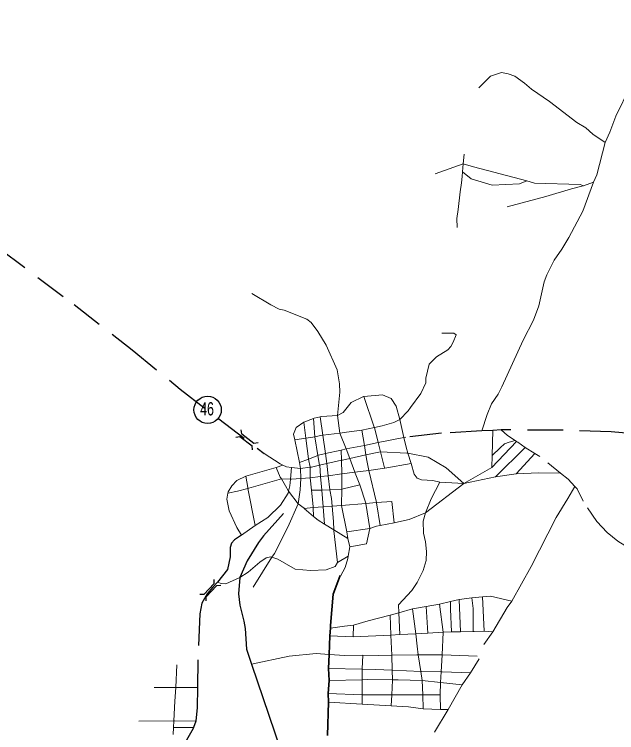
# Model space of a CAD drawing. Extents: x 423 to 448.8, y 7456.3 to 7484.
# Drawn here: x 441.806 to 445.463, y 7458.991 to 7463.35 of the extents above; entities that cross this region are included whole.
import ezdxf
from ezdxf.enums import TextEntityAlignment as Align

# ---------------------------------------------------------------- set-up
doc = ezdxf.new("R2010")
doc.units = 0
doc.header["$LTSCALE"] = 0.032
doc.linetypes.add('LONG_DASHED', pattern=[7.5, 6, -1.5])
doc.linetypes.add('MEDIUM_DASHED', pattern=[4.5, 3, -1.5])
for name, color, linetype, lineweight in [('10', 7, 'Continuous', 25), ('13', 7, 'Continuous', 25), ('15', 7, 'Continuous', 25), ('2', 7, 'Continuous', 35), ('4', 7, 'LONG_DASHED', 25), ('5', 7, 'LONG_DASHED', 13), ('6', 7, 'MEDIUM_DASHED', 13), ('7', 7, 'Continuous', 13), ('8', 7, 'Continuous', 13)]:
    doc.layers.add(name, color=color, linetype=linetype, lineweight=lineweight)
doc.layers.add('61', color=7, linetype='Continuous')

msp = doc.modelspace()

# ---------------------------------------------------------------- linework, layer by layer
at = {"layer": '10'}
for p, q in [((443.1866, 7460.8036), (443.1831, 7460.8283)), ((443.1501, 7460.7839), (443.1746, 7460.7876)), ((443.1746, 7460.7876), (443.2488, 7460.7324)), ((443.2525, 7460.7077), (443.2488, 7460.7324)), ((442.9705, 7459.8155), (443.0342, 7459.8825)), ((443.0592, 7459.8832), (443.0342, 7459.8825)), ((442.956, 7459.8292), (442.9311, 7459.8288)), ((442.9712, 7459.7907), (442.9705, 7459.8155))]:
    msp.add_line(p, q, dxfattribs=at)
for points in [[(443.1866, 7460.8036), (443.2608, 7460.7484), (443.2855, 7460.752)], [(442.956, 7459.8292), (443.0197, 7459.8963), (443.0191, 7459.9213)]]:
    msp.add_lwpolyline(points, dxfattribs=at)
at = {"layer": '13'}
msp.add_circle((442.9795, 7460.9502), 0.083, dxfattribs=at)
at = {"layer": '15'}
msp.add_lwpolyline([(443.4399, 7460.3212), (443.3192, 7460.186), (443.2888, 7460.1444), (443.2185, 7460.0341), (443.1755, 7459.9315), (443.1664, 7459.834), (443.1747, 7459.7637), (443.1986, 7459.6682), (443.2077, 7459.6227), (443.2157, 7459.4976), (443.2466, 7459.4065), (443.3513, 7459.0974), (443.4241, 7458.8825)], dxfattribs=at)
at = {"layer": '2'}
msp.add_lwpolyline([(443.7841, 7459.9454), (443.7413, 7459.8304), (443.7261, 7459.6406), (443.7247, 7459.6256), (443.7204, 7459.5783), (443.7165, 7459.4659), (443.7135, 7459.3795), (443.7181, 7459.3082), (443.7106, 7459.229), (443.7131, 7459.1759), (443.7079, 7458.9733)], dxfattribs=at)
at = {"layer": '4'}
for points in [[(439.8809, 7463.4977), (439.941, 7463.3465), (439.9475, 7463.3074), (439.9461, 7463.2713), (440.0002, 7463.2519), (440.0853, 7463.2005), (440.6229, 7462.7659), (440.6856, 7462.7187), (440.7238, 7462.6981), (440.7575, 7462.6654), (440.987, 7462.492), (441.1811, 7462.3354), (441.3202, 7462.2232), (441.6114, 7462.0058), (441.6724, 7461.9545), (441.7153, 7461.9277), (442.1688, 7461.5884), (442.5212, 7461.3144), (442.8129, 7461.0757), (443.0484, 7460.8955), (443.3233, 7460.6842)], [(445.5939, 7460.8017), (445.429, 7460.8155), (445.1129, 7460.8267), (444.7608, 7460.8281), (444.712, 7460.8254), (444.6433, 7460.8215), (444.3984, 7460.8078), (444.1834, 7460.784)], [(443.1856, 7460.1903), (443.1416, 7460.1609), (443.1247, 7460.1402), (443.1167, 7460.1151), (443.1165, 7460.0571), (443.1, 7459.9818), (443.0398, 7459.9036), (443.0108, 7459.8732), (442.9765, 7459.8343), (442.9443, 7459.7763), (442.9315, 7459.7119), (442.9194, 7459.4337), (442.9179, 7459.2659), (442.9168, 7459.1434), (442.9073, 7459.0609), (442.8937, 7459.0222), (442.8916, 7459.017), (442.8511, 7458.9445)]]:
    msp.add_lwpolyline(points, dxfattribs=at)
at = {"layer": '5'}
msp.add_lwpolyline([(443.2484, 7461.6551), (443.3632, 7461.587), (443.4134, 7461.5601), (443.4451, 7461.5541), (443.5825, 7461.5), (443.6074, 7461.4794), (443.6495, 7461.4262), (443.7001, 7461.3417), (443.7655, 7461.1933), (443.7808, 7461.1078), (443.7823, 7461.0565), (443.7687, 7460.9163)], dxfattribs=at)
at = {"layer": '6'}
msp.add_lwpolyline([(445.687, 7460.0021), (445.555, 7460.1006), (445.4699, 7460.1526), (445.4053, 7460.206), (445.3418, 7460.2718), (445.2585, 7460.3961), (445.2222, 7460.4702), (445.2083, 7460.4855), (445.1688, 7460.5289), (445.1225, 7460.5647), (444.9972, 7460.6675), (444.9652, 7460.6849), (444.9077, 7460.7213), (444.8634, 7460.7534), (444.8557, 7460.7584), (444.8458, 7460.7648), (444.8001, 7460.7943), (444.7608, 7460.8281)], dxfattribs=at)
at = {"layer": '7'}
msp.add_line((445.3218, 7462.3319), (445.2609, 7462.3096), dxfattribs=at)
for points in [[(445.3932, 7462.5717), (445.4216, 7462.6344), (445.4568, 7462.7319), (445.5458, 7462.9103), (445.6652, 7463.0789), (445.7851, 7463.2073)], [(445.3932, 7462.5717), (445.3178, 7462.6225), (445.2752, 7462.6618), (445.2211, 7462.6929), (445.0557, 7462.8205), (444.946, 7462.8968), (444.9034, 7462.9313), (444.8444, 7462.9739), (444.8035, 7462.9895), (444.7641, 7462.9977), (444.697, 7462.9747), (444.6266, 7462.9042)], [(445.3218, 7462.3319), (445.3424, 7462.376), (445.3932, 7462.5717)], [(444.5371, 7462.501), (444.531, 7462.4431), (444.531, 7462.4426), (444.5274, 7462.395)], [(444.917, 7462.3386), (444.5929, 7462.4239), (444.5316, 7462.4428), (444.531, 7462.4426), (444.3599, 7462.3827)], [(444.5274, 7462.395), (444.5253, 7462.3654), (444.5214, 7462.3281), (444.5117, 7462.2737), (444.4999, 7462.1648), (444.4923, 7462.1104), (444.4936, 7462.0567)], [(444.5274, 7462.395), (444.579, 7462.3525), (444.7074, 7462.3127), (444.8737, 7462.3214), (444.917, 7462.3386)], [(444.6433, 7460.8215), (444.6756, 7460.9209), (444.7036, 7460.986), (444.7432, 7461.0455), (444.7653, 7461.0893), (444.8948, 7461.372), (444.9583, 7461.4932), (444.9893, 7461.5816), (445.0236, 7461.7276), (445.0382, 7461.7688), (445.0829, 7461.8573), (445.1292, 7461.9243), (445.173, 7461.9947), (445.2583, 7462.1545), (445.3218, 7462.3319)], [(445.2609, 7462.3096), (445.2405, 7462.3179), (444.9634, 7462.325), (444.917, 7462.3386)], [(445.2609, 7462.3096), (445.2603, 7462.3094), (445.1884, 7462.2907), (445.0327, 7462.2453), (444.7973, 7462.181)]]:
    msp.add_lwpolyline(points, dxfattribs=at)
at = {"layer": '8'}
for p, q in [((443.7687, 7460.9163), (443.7816, 7460.8092)), ((443.5082, 7460.7675), (443.5765, 7460.778)), ((444.8557, 7460.7584), (444.7043, 7460.6001)), ((444.7263, 7460.5431), (444.9077, 7460.7213)), ((444.0284, 7460.6957), (443.9401, 7460.676)), ((444.8531, 7460.5624), (444.9652, 7460.6849)), ((443.601, 7460.6018), (443.5927, 7460.6509)), ((443.4821, 7460.5298), (443.4889, 7460.6003)), ((443.5434, 7460.5942), (443.4889, 7460.6003)), ((443.5434, 7460.5942), (443.601, 7460.6018)), ((444.7043, 7460.6001), (444.5356, 7460.5025)), ((444.3025, 7460.325), (444.5356, 7460.5025)), ((443.6723, 7460.4629), (443.6097, 7460.4629)), ((443.6228, 7460.3024), (443.6206, 7460.3563)), ((443.824, 7460.2091), (443.964, 7460.2306)), ((443.8316, 7460.1699), (443.8425, 7460.1188)), ((443.8331, 7460.0616), (443.8425, 7460.1188)), ((443.7679, 7460.0245), (443.8331, 7460.0616)), ((444.5064, 7459.7996), (444.5146, 7459.6027)), ((444.6589, 7459.6069), (444.6492, 7459.816)), ((444.3059, 7459.7567), (444.316, 7459.5953)), ((444.1403, 7459.7185), (444.1461, 7459.5863)), ((443.8637, 7459.5718), (443.8659, 7459.6433)), ((443.8637, 7459.5718), (443.7204, 7459.5783)), ((444.316, 7459.5953), (444.2429, 7459.5914)), ((444.5909, 7459.6047), (444.5146, 7459.6027)), ((444.7102, 7459.6019), (444.6569, 7459.5262)), ((444.7102, 7459.6019), (444.6589, 7459.6069)), ((444.5753, 7459.3548), (444.6277, 7459.4387)), ((443.7135, 7459.3795), (443.9174, 7459.3753)), ((443.7181, 7459.3082), (443.9173, 7459.3122)), ((442.6545, 7459.2647), (442.787, 7459.2654)), ((443.917, 7459.1635), (443.7131, 7459.1759)), ((444.3574, 7458.9938), (444.4398, 7459.1305)), ((442.8937, 7459.0222), (442.7724, 7459.0214))]:
    msp.add_line(p, q, dxfattribs=at)
for points in [[(444.4019, 7461.4161), (444.4748, 7461.4158), (444.4877, 7461.4047), (444.4705, 7461.3609), (444.4568, 7461.3351), (444.437, 7461.3136), (444.3691, 7461.2724), (444.3245, 7461.2261), (444.3052, 7461.1414), (444.3052, 7461.1136), (444.2738, 7461.0491), (444.212, 7460.9641), (444.1965, 7460.9435), (444.1455, 7460.8912), (444.1708, 7460.7815)], [(443.9282, 7461.0318), (443.926, 7461.0316), (443.8515, 7460.9947), (443.8017, 7460.9338), (443.7687, 7460.9163)], [(444.1455, 7460.8912), (444.1238, 7460.9728), (444.0943, 7461.018), (444.0419, 7461.0419), (443.9282, 7461.0318)], [(443.9916, 7460.843), (443.9912, 7460.8446), (443.9282, 7461.0318)], [(443.6617, 7460.9081), (443.6265, 7460.8989), (443.6226, 7460.8974), (443.5642, 7460.8747)], [(443.6655, 7460.5445), (443.6597, 7460.6134), (443.6596, 7460.6142), (443.6495, 7460.6729), (443.63, 7460.7869), (443.6226, 7460.8974)], [(443.7687, 7460.9163), (443.6702, 7460.9103), (443.6617, 7460.9081)], [(443.7035, 7460.6242), (443.7, 7460.654), (443.6955, 7460.6841), (443.6785, 7460.7969), (443.6617, 7460.9081)], [(443.9916, 7460.843), (444.04, 7460.8536), (444.1092, 7460.8731), (444.1455, 7460.8912)], [(443.5642, 7460.8747), (443.5635, 7460.8744), (443.5176, 7460.8424), (443.501, 7460.8021), (443.5082, 7460.7675), (443.5377, 7460.6295), (443.5434, 7460.5942)], [(443.5927, 7460.6509), (443.5924, 7460.6525), (443.5765, 7460.778), (443.5642, 7460.8747)], [(443.7816, 7460.8092), (443.8225, 7460.8141), (443.9164, 7460.8264), (443.9916, 7460.843)], [(444.0284, 7460.6957), (444.0146, 7460.7509), (443.9916, 7460.843)], [(443.63, 7460.7869), (443.6757, 7460.7966), (443.6785, 7460.7969), (443.7816, 7460.8092)], [(443.7816, 7460.8092), (443.7817, 7460.8083), (443.8198, 7460.7126), (443.8421, 7460.6541), (443.8738, 7460.5709)], [(443.9577, 7460.5816), (443.9453, 7460.643), (443.9401, 7460.676), (443.9309, 7460.7344), (443.9164, 7460.8264)], [(444.7043, 7460.6001), (444.7071, 7460.6738), (444.712, 7460.8254)], [(443.5765, 7460.778), (443.6184, 7460.7844), (443.63, 7460.7869)], [(443.8198, 7460.7126), (443.9309, 7460.7344), (444.0146, 7460.7509), (444.1708, 7460.7815), (444.1834, 7460.784)], [(444.1708, 7460.7815), (444.1843, 7460.7227), (444.195, 7460.6867)], [(444.7071, 7460.6738), (444.7557, 7460.72), (444.7816, 7460.7441), (444.81, 7460.7547), (444.8458, 7460.7648)], [(443.6955, 7460.6841), (443.7905, 7460.7054), (443.8198, 7460.7126)], [(443.7947, 7460.5609), (443.7923, 7460.6442), (443.7905, 7460.7054)], [(443.4889, 7460.6003), (443.4592, 7460.6036), (443.4367, 7460.614), (443.4189, 7460.6223), (443.3233, 7460.6842)], [(443.5377, 7460.6295), (443.5927, 7460.6509), (443.6495, 7460.6729)], [(443.6495, 7460.6729), (443.6533, 7460.6744), (443.6955, 7460.6841)], [(443.9401, 7460.676), (443.8432, 7460.6543), (443.8421, 7460.6541)], [(444.195, 7460.6867), (444.1888, 7460.6879), (444.0284, 7460.6957), (444.054, 7460.5973), (444.0545, 7460.5953)], [(444.195, 7460.6867), (444.1952, 7460.686), (444.2157, 7460.6237)], [(444.195, 7460.6867), (444.3191, 7460.663), (444.4272, 7460.5987), (444.5356, 7460.5025)], [(443.8421, 7460.6541), (443.7973, 7460.6453), (443.7923, 7460.6442), (443.7035, 7460.6242), (443.6596, 7460.6142)], [(443.7348, 7460.3654), (443.7308, 7460.4123), (443.7223, 7460.4649), (443.7122, 7460.5504), (443.7035, 7460.6242)], [(444.2157, 7460.6237), (444.0545, 7460.5953), (443.9577, 7460.5816), (444.0042, 7460.3866)], [(444.5356, 7460.5025), (444.3888, 7460.5111), (444.3477, 7460.5203), (444.2776, 7460.5244), (444.2525, 7460.536), (444.2334, 7460.5605), (444.2157, 7460.6237)], [(443.2122, 7460.5483), (443.395, 7460.5999), (443.4367, 7460.614)], [(443.395, 7460.5999), (443.4208, 7460.5423), (443.4277, 7460.5305)], [(443.9577, 7460.5816), (443.8738, 7460.5709), (443.7947, 7460.5609), (443.7122, 7460.5504), (443.6655, 7460.5445), (443.6019, 7460.5364), (443.5457, 7460.5342), (443.5434, 7460.5942)], [(443.6596, 7460.6142), (443.6097, 7460.603), (443.601, 7460.6018)], [(443.601, 7460.6018), (443.601, 7460.6016), (443.6019, 7460.5364)], [(443.1026, 7460.4442), (443.104, 7460.4518), (443.1261, 7460.4897), (443.1565, 7460.5216), (443.2122, 7460.5483)], [(443.2122, 7460.5483), (443.2225, 7460.4778), (443.2236, 7460.4724), (443.2673, 7460.2475)], [(443.4277, 7460.5305), (443.2295, 7460.4739), (443.2236, 7460.4724)], [(443.4821, 7460.5298), (443.429, 7460.5309), (443.4277, 7460.5305)], [(443.4277, 7460.5305), (443.4518, 7460.4893), (443.4714, 7460.4558)], [(443.4714, 7460.4558), (443.478, 7460.4879), (443.4821, 7460.5298)], [(443.5457, 7460.5342), (443.4892, 7460.5296), (443.4821, 7460.5298)], [(443.5286, 7460.3805), (443.542, 7460.4645), (443.5457, 7460.5342)], [(443.6206, 7460.3563), (443.6204, 7460.3624), (443.6097, 7460.4629), (443.6019, 7460.5364)], [(443.6655, 7460.5445), (443.6723, 7460.4629), (443.6809, 7460.3611), (443.6897, 7460.2556)], [(443.7938, 7460.4693), (443.7948, 7460.5568), (443.7947, 7460.5609)], [(443.8738, 7460.5709), (443.8756, 7460.5663), (443.9037, 7460.4944)], [(444.5356, 7460.5025), (444.7263, 7460.5431), (444.8531, 7460.5624), (444.991, 7460.5681), (445.1225, 7460.5647)], [(443.7223, 7460.4649), (443.793, 7460.4691), (443.7938, 7460.4693), (443.9037, 7460.4944)], [(443.9037, 7460.4944), (443.9397, 7460.383), (443.9399, 7460.3815), (443.964, 7460.2306)], [(444.1403, 7459.7185), (444.1382, 7459.7659), (444.2201, 7459.8535), (444.2524, 7459.9026), (444.2877, 7459.9758), (444.3066, 7460.0366), (444.3091, 7460.0897), (444.3022, 7460.1499), (444.2906, 7460.2011), (444.2887, 7460.2749), (444.3025, 7460.325), (444.3356, 7460.4097), (444.3888, 7460.5111)], [(444.8269, 7459.7887), (444.9446, 7459.9996), (445.0956, 7460.297), (445.1656, 7460.4123), (445.2083, 7460.4855)], [(443.1026, 7460.4442), (443.0956, 7460.4075), (443.111, 7460.3373), (443.1565, 7460.2358), (443.1856, 7460.1903), (443.2673, 7460.2475), (443.3448, 7460.2963), (443.4218, 7460.3714), (443.469, 7460.4442), (443.4714, 7460.4558)], [(443.2236, 7460.4724), (443.16, 7460.456), (443.1026, 7460.4442)], [(443.5657, 7460.352), (443.5649, 7460.3527), (443.5286, 7460.3805), (443.4714, 7460.4558)], [(443.6723, 7460.4629), (443.6736, 7460.4629), (443.7223, 7460.4649)], [(443.7928, 7460.3699), (443.7927, 7460.3707), (443.7938, 7460.4693)], [(443.5286, 7460.3805), (443.4655, 7460.2375), (443.3845, 7460.0787), (443.3699, 7460.0555), (443.2552, 7459.8734)], [(443.5657, 7460.352), (443.6206, 7460.3563), (443.6809, 7460.3611), (443.7348, 7460.3654), (443.7928, 7460.3699), (443.9399, 7460.3815), (444.0042, 7460.3866)], [(443.7459, 7460.2217), (443.7429, 7460.2717), (443.7348, 7460.3654)], [(443.8316, 7460.1699), (443.824, 7460.2091), (443.7928, 7460.3699)], [(444.0042, 7460.3866), (444.0977, 7460.394), (444.1116, 7460.2639)], [(444.0042, 7460.3866), (444.0044, 7460.3856), (444.0267, 7460.2477)], [(443.6897, 7460.2556), (443.65, 7460.2796), (443.6228, 7460.3024), (443.5657, 7460.352)], [(444.0267, 7460.2477), (444.1116, 7460.2639), (444.1196, 7460.2654), (444.2031, 7460.2841), (444.3025, 7460.325)], [(443.8316, 7460.1699), (443.7459, 7460.2217), (443.6897, 7460.2556)], [(443.8425, 7460.1188), (443.9436, 7460.1377), (443.964, 7460.2306)], [(443.964, 7460.2306), (444.0046, 7460.2435), (444.0267, 7460.2477)], [(443.7679, 7460.0245), (443.7462, 7460.216), (443.7459, 7460.2217)], [(443.0398, 7459.9036), (443.0622, 7459.8956), (443.0897, 7459.8949), (443.1755, 7459.9315), (443.2246, 7459.9646), (443.2972, 7460.0261), (443.3338, 7460.0512), (443.3612, 7460.0582), (443.3699, 7460.0555)], [(443.3699, 7460.0555), (443.4064, 7460.0439), (443.51, 7459.9826), (443.6042, 7459.9747), (443.6993, 7459.9781), (443.7533, 7459.9988), (443.7679, 7460.0245)], [(443.8331, 7460.0616), (443.8308, 7460.0478), (443.814, 7459.9934), (443.7854, 7459.9415), (443.7841, 7459.9454)], [(444.3879, 7459.7707), (444.4539, 7459.7868), (444.5064, 7459.7996), (444.5825, 7459.8101), (444.6492, 7459.816)], [(444.5825, 7459.8101), (444.591, 7459.7443), (444.5909, 7459.6047)], [(444.6492, 7459.816), (444.697, 7459.8201), (444.8269, 7459.7887)], [(444.8269, 7459.7887), (444.7975, 7459.7506), (444.7102, 7459.6019)], [(444.1403, 7459.7185), (444.2231, 7459.742), (444.3059, 7459.7567), (444.3879, 7459.7707)], [(444.4096, 7459.6006), (444.4096, 7459.6015), (444.3879, 7459.7707)], [(444.4539, 7459.7868), (444.4542, 7459.7394), (444.4594, 7459.6035)], [(443.8659, 7459.6433), (443.954, 7459.6705), (444.0883, 7459.7035), (444.1396, 7459.7183), (444.1403, 7459.7185)], [(444.0883, 7459.7035), (444.0927, 7459.5835), (444.0971, 7459.4607), (444.1004, 7459.3694), (444.1025, 7459.3111)], [(444.2586, 7459.4641), (444.2511, 7459.5165), (444.2429, 7459.5911), (444.2429, 7459.5914), (444.2231, 7459.742)], [(443.8659, 7459.6433), (443.8095, 7459.6372), (443.7247, 7459.6256)], [(444.2429, 7459.5914), (444.1461, 7459.5863), (444.0927, 7459.5835), (443.8637, 7459.5718)], [(444.5146, 7459.6027), (444.4594, 7459.6035), (444.4096, 7459.6006), (444.316, 7459.5953)], [(444.394, 7459.2948), (444.3973, 7459.3595), (444.4025, 7459.4628), (444.4096, 7459.6006)], [(444.6589, 7459.6069), (444.5982, 7459.6049), (444.5909, 7459.6047)], [(444.0971, 7459.4607), (444.017, 7459.4589), (443.9208, 7459.4617), (443.8134, 7459.4585), (443.7165, 7459.4659), (443.6387, 7459.4719), (443.4743, 7459.456), (443.2466, 7459.4065)], [(443.9208, 7459.4617), (443.9174, 7459.3783), (443.9174, 7459.3753), (443.9173, 7459.3122), (443.9171, 7459.2211), (443.917, 7459.1635)], [(444.2586, 7459.4641), (444.2486, 7459.4642), (444.0971, 7459.4607)], [(444.6158, 7459.456), (444.4055, 7459.4628), (444.4025, 7459.4628), (444.2586, 7459.4641)], [(444.2586, 7459.4641), (444.2731, 7459.3622), (444.281, 7459.3072), (444.2851, 7459.2199), (444.289, 7459.1357)], [(442.7925, 7459.4029), (442.787, 7459.2654), (442.9179, 7459.2659)], [(443.9174, 7459.3753), (443.9979, 7459.3736), (444.1004, 7459.3694), (444.2731, 7459.3622)], [(444.2731, 7459.3622), (444.278, 7459.362), (444.3973, 7459.3595)], [(444.3973, 7459.3595), (444.4035, 7459.3594), (444.5753, 7459.3548)], [(444.4398, 7459.1305), (444.5238, 7459.2803), (444.5753, 7459.3548)], [(443.9173, 7459.3122), (443.9488, 7459.3128), (444.1025, 7459.3111)], [(444.1025, 7459.3111), (444.1026, 7459.3093), (444.0972, 7459.2205), (444.0932, 7459.1533)], [(444.1025, 7459.3111), (444.1372, 7459.3107), (444.281, 7459.3072), (444.394, 7459.2948)], [(442.787, 7459.2654), (442.7811, 7459.1812), (442.7745, 7459.0619)], [(444.5238, 7459.2803), (444.394, 7459.2948), (444.3918, 7459.2195)], [(443.9171, 7459.2211), (443.9148, 7459.2211), (443.7106, 7459.229)], [(444.3918, 7459.2195), (444.2851, 7459.2199), (444.0972, 7459.2205), (443.9171, 7459.2211)], [(444.3918, 7459.2195), (444.3918, 7459.2192), (444.3931, 7459.1321)], [(444.289, 7459.1357), (444.1995, 7459.1472), (444.0932, 7459.1533), (443.917, 7459.1635)], [(444.289, 7459.1357), (444.3931, 7459.1321), (444.4398, 7459.1305)], [(442.9073, 7459.0609), (442.7791, 7459.0619), (442.7745, 7459.0619), (442.5617, 7459.0615)], [(442.7745, 7459.0619), (442.7724, 7459.0214), (442.7707, 7458.9793)]]:
    msp.add_lwpolyline(points, dxfattribs=at)

# ---------------------------------------------------------------- texts
at = {"layer": '61', "width": 0.7}
msp.add_text('46', height=0.08, dxfattribs=at).set_placement((442.976, 7460.9162), align=Align.CENTER)

doc.saveas('drawing.dxf')
